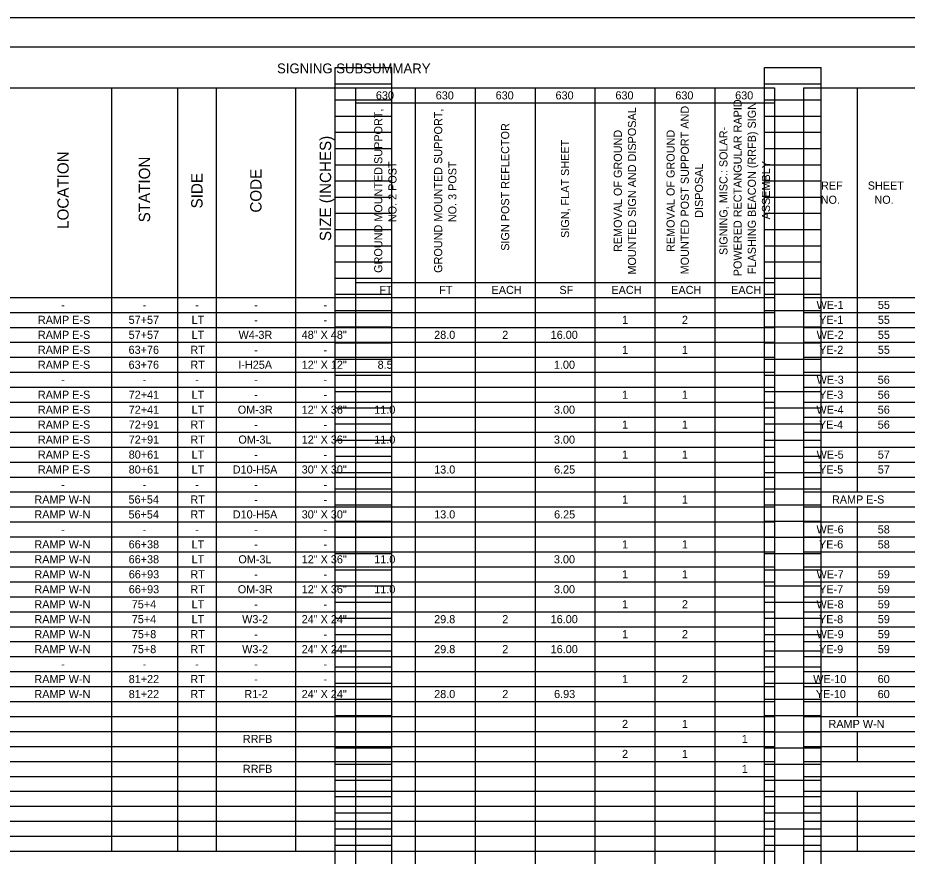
# Model space of a CAD drawing. Extents: x -6.8 to 34, y 0 to 22.
# Drawn here: x 3.36 to 18.73, y 7.51 to 22 of the extents above; entities that cross this region are included whole.
import ezdxf

# ---------------------------------------------------------------- set-up
doc = ezdxf.new("R2010")
doc.units = 0
for name, color, linetype in [('SH_Border', 7, 'Continuous'), ('SH_Cut_Line', 7, 'Continuous'), ('SH_Data', 7, 'Continuous'), ('SH_Text', 7, 'Continuous')]:
    doc.layers.add(name, color=color, linetype=linetype)

msp = doc.modelspace()

# ---------------------------------------------------------------- linework, layer by layer
at = {"layer": 'SH_Border'}
msp.add_lwpolyline([(1.5, 21.5), (33.5, 21.5), (33.5, 0.5), (1.5, 0.5)], close=True, dxfattribs=at)
at = {"layer": 'SH_Cut_Line'}
msp.add_lwpolyline([(0, 0), (34, 0), (34, 22), (0, 22)], close=True, dxfattribs=at)
at = {"layer": 'SH_Data'}
for p, q in [((8.84, 0.98), (8.84, 21.14)), ((8.84, 21.14), (9.82, 21.14)), ((9.82, 0.98), (9.82, 21.14)), ((16.26, 0.98), (16.26, 21.14)), ((16.26, 21.14), (17.24, 21.14)), ((17.24, 0.98), (17.24, 21.14)), ((8.84, 20.86), (9.82, 20.86)), ((16.26, 20.86), (17.24, 20.86)), ((8.84, 20.58), (9.82, 20.58)), ((16.26, 20.58), (17.24, 20.58)), ((8.84, 20.3), (9.82, 20.3)), ((16.26, 20.3), (17.24, 20.3)), ((8.84, 20.02), (9.82, 20.02)), ((16.26, 20.02), (17.24, 20.02)), ((8.84, 19.74), (9.82, 19.74)), ((16.26, 19.74), (17.24, 19.74)), ((8.84, 19.46), (9.82, 19.46)), ((16.26, 19.46), (17.24, 19.46)), ((8.84, 19.18), (9.82, 19.18)), ((16.26, 19.18), (17.24, 19.18)), ((8.84, 18.9), (9.82, 18.9)), ((16.26, 18.9), (17.24, 18.9)), ((8.84, 18.62), (9.82, 18.62)), ((16.26, 18.62), (17.24, 18.62)), ((8.84, 18.34), (9.82, 18.34)), ((16.26, 18.34), (17.24, 18.34)), ((8.84, 18.06), (9.82, 18.06)), ((16.26, 18.06), (17.24, 18.06)), ((8.84, 17.78), (9.82, 17.78)), ((16.26, 17.78), (17.24, 17.78)), ((8.84, 17.5), (9.82, 17.5)), ((16.26, 17.5), (17.24, 17.5)), ((8.84, 17.22), (9.82, 17.22)), ((16.26, 17.22), (17.24, 17.22)), ((8.84, 16.94), (9.82, 16.94)), ((16.26, 16.94), (17.24, 16.94)), ((8.84, 16.66), (9.82, 16.66)), ((16.26, 16.66), (17.24, 16.66)), ((8.84, 16.38), (9.82, 16.38)), ((16.26, 16.38), (17.24, 16.38)), ((8.84, 16.1), (9.82, 16.1)), ((16.26, 16.1), (17.24, 16.1)), ((8.84, 15.82), (9.82, 15.82)), ((16.26, 15.82), (17.24, 15.82)), ((8.84, 15.54), (9.82, 15.54)), ((16.26, 15.54), (17.24, 15.54)), ((8.84, 15.26), (9.82, 15.26)), ((16.26, 15.26), (17.24, 15.26)), ((8.84, 14.98), (9.82, 14.98)), ((16.26, 14.98), (17.24, 14.98)), ((8.84, 14.7), (9.82, 14.7)), ((16.26, 14.7), (17.24, 14.7)), ((8.84, 14.42), (9.82, 14.42)), ((16.26, 14.42), (17.24, 14.42)), ((8.84, 14.14), (9.82, 14.14)), ((16.26, 14.14), (17.24, 14.14)), ((8.84, 13.86), (9.82, 13.86)), ((16.26, 13.86), (17.24, 13.86)), ((8.84, 13.58), (9.82, 13.58)), ((16.26, 13.58), (17.24, 13.58)), ((8.84, 13.3), (9.82, 13.3)), ((16.26, 13.3), (17.24, 13.3)), ((8.84, 13.02), (9.82, 13.02)), ((16.26, 13.02), (17.24, 13.02)), ((8.84, 12.74), (9.82, 12.74)), ((16.26, 12.74), (17.24, 12.74)), ((8.84, 12.46), (9.82, 12.46)), ((16.26, 12.46), (17.24, 12.46)), ((8.84, 12.18), (9.82, 12.18)), ((16.26, 12.18), (17.24, 12.18)), ((8.84, 11.9), (9.82, 11.9)), ((16.26, 11.9), (17.24, 11.9)), ((8.84, 11.62), (9.82, 11.62)), ((16.26, 11.62), (17.24, 11.62)), ((8.84, 11.34), (9.82, 11.34)), ((16.26, 11.34), (17.24, 11.34)), ((8.84, 11.06), (9.82, 11.06)), ((16.26, 11.06), (17.24, 11.06)), ((8.84, 10.78), (9.82, 10.78)), ((16.26, 10.78), (17.24, 10.78)), ((8.84, 10.5), (9.82, 10.5)), ((16.26, 10.5), (17.24, 10.5)), ((8.84, 10.22), (9.82, 10.22)), ((16.26, 10.22), (17.24, 10.22)), ((8.84, 9.94), (9.82, 9.94)), ((16.26, 9.94), (17.24, 9.94)), ((8.84, 9.66), (9.82, 9.66)), ((16.26, 9.66), (17.24, 9.66)), ((8.84, 9.38), (9.82, 9.38)), ((16.26, 9.38), (17.24, 9.38)), ((8.84, 9.1), (9.82, 9.1)), ((16.26, 9.1), (17.24, 9.1)), ((8.84, 8.82), (9.82, 8.82)), ((16.26, 8.82), (17.24, 8.82)), ((8.84, 8.54), (9.82, 8.54)), ((16.26, 8.54), (17.24, 8.54)), ((8.84, 8.26), (9.82, 8.26)), ((16.26, 8.26), (17.24, 8.26)), ((8.84, 7.98), (9.82, 7.98)), ((16.26, 7.98), (17.24, 7.98)), ((8.84, 7.7), (9.82, 7.7)), ((16.26, 7.7), (17.24, 7.7))]:
    msp.add_line(p, q, dxfattribs=at)
at = {"layer": 'SH_Text'}
for p, q in [((1.872, 20.788), (16.435, 20.788)), ((4.977, 20.788), (4.977, 7.595)), ((6.118, 20.788), (6.118, 7.595)), ((6.788, 20.788), (6.788, 7.595)), ((8.157, 20.788), (8.157, 7.595)), ((9.192, 20.788), (9.192, 7.078)), ((10.227, 20.788), (10.227, 7.078)), ((11.262, 20.788), (11.262, 7.078)), ((12.296, 20.788), (12.296, 7.078)), ((13.331, 20.788), (13.331, 7.078)), ((14.366, 20.788), (14.366, 7.078)), ((15.401, 20.788), (15.401, 7.078)), ((16.435, 20.788), (16.435, 7.078)), ((16.932, 20.788), (31.662, 20.788)), ((16.932, 20.788), (16.932, 7.078)), ((17.86, 20.788), (17.86, 13.804)), ((9.192, 20.53), (16.435, 20.53)), ((9.192, 17.425), (16.435, 17.425)), ((1.872, 17.167), (16.435, 17.167)), ((16.932, 17.167), (31.662, 17.167)), ((1.872, 16.908), (16.435, 16.908)), ((16.932, 16.908), (31.662, 16.908)), ((1.872, 16.649), (16.435, 16.649)), ((16.932, 16.649), (31.662, 16.649)), ((1.872, 16.391), (16.435, 16.391)), ((16.932, 16.391), (31.662, 16.391)), ((1.872, 16.132), (16.435, 16.132)), ((16.932, 16.132), (31.662, 16.132)), ((1.872, 15.873), (16.435, 15.873)), ((16.932, 15.873), (31.662, 15.873)), ((1.872, 15.615), (16.435, 15.615)), ((16.932, 15.615), (31.662, 15.615)), ((1.872, 15.356), (16.435, 15.356)), ((16.932, 15.356), (31.662, 15.356)), ((1.872, 15.097), (16.435, 15.097)), ((16.932, 15.097), (31.662, 15.097)), ((1.872, 14.838), (16.435, 14.838)), ((16.932, 14.838), (31.662, 14.838)), ((1.872, 14.58), (16.435, 14.58)), ((16.932, 14.58), (31.662, 14.58)), ((1.872, 14.321), (16.435, 14.321)), ((16.932, 14.321), (31.662, 14.321)), ((1.872, 14.062), (16.435, 14.062)), ((16.932, 14.062), (31.662, 14.062)), ((1.872, 13.804), (16.435, 13.804)), ((16.932, 13.804), (31.662, 13.804)), ((1.872, 13.545), (16.435, 13.545)), ((16.932, 13.545), (31.662, 13.545)), ((17.86, 13.545), (17.86, 9.923)), ((1.872, 13.286), (16.435, 13.286)), ((16.932, 13.286), (31.662, 13.286)), ((1.872, 13.028), (16.435, 13.028)), ((16.932, 13.028), (31.662, 13.028)), ((1.872, 12.769), (16.435, 12.769)), ((16.932, 12.769), (31.662, 12.769)), ((1.872, 12.51), (16.435, 12.51)), ((16.932, 12.51), (31.662, 12.51)), ((1.872, 12.251), (16.435, 12.251)), ((16.932, 12.251), (31.662, 12.251)), ((1.872, 11.993), (16.435, 11.993)), ((16.932, 11.993), (31.662, 11.993)), ((1.872, 11.734), (16.435, 11.734)), ((16.932, 11.734), (31.662, 11.734)), ((1.872, 11.475), (16.435, 11.475)), ((16.932, 11.475), (31.662, 11.475)), ((1.872, 11.217), (16.435, 11.217)), ((16.932, 11.217), (31.662, 11.217)), ((1.872, 10.958), (16.435, 10.958)), ((16.932, 10.958), (31.662, 10.958)), ((1.872, 10.699), (16.435, 10.699)), ((16.932, 10.699), (31.662, 10.699)), ((1.872, 10.441), (16.435, 10.441)), ((16.932, 10.441), (31.662, 10.441)), ((1.872, 10.182), (16.435, 10.182)), ((16.932, 10.182), (31.662, 10.182)), ((1.872, 9.923), (16.435, 9.923)), ((16.932, 9.923), (31.662, 9.923)), ((1.872, 9.665), (16.435, 9.665)), ((16.932, 9.665), (31.662, 9.665)), ((17.86, 9.665), (17.86, 9.147)), ((1.872, 9.406), (16.435, 9.406)), ((16.932, 9.406), (31.662, 9.406)), ((1.872, 9.147), (16.435, 9.147)), ((16.932, 9.147), (31.662, 9.147)), ((1.872, 8.888), (16.435, 8.888)), ((16.932, 8.888), (31.662, 8.888)), ((1.872, 8.63), (16.435, 8.63)), ((16.932, 8.63), (31.662, 8.63)), ((17.86, 8.63), (17.86, 7.595)), ((1.872, 8.371), (16.435, 8.371)), ((16.932, 8.371), (31.662, 8.371)), ((1.872, 8.112), (16.435, 8.112)), ((16.932, 8.112), (31.662, 8.112)), ((1.872, 7.854), (16.435, 7.854)), ((16.932, 7.854), (31.662, 7.854)), ((1.872, 7.595), (9.192, 7.595)), ((9.192, 7.595), (16.435, 7.595)), ((16.932, 7.595), (31.662, 7.595))]:
    msp.add_line(p, q, dxfattribs=at)

# ---------------------------------------------------------------- texts
for s, height, p in [('SIGNING SUBSUMMARY', 0.17, (7.838, 21.04)), ('630', 0.14, (9.546, 20.589)), ('630', 0.14, (10.58, 20.589)), ('630', 0.14, (11.615, 20.589)), ('630', 0.14, (12.65, 20.589)), ('630', 0.14, (13.685, 20.589)), ('630', 0.14, (14.72, 20.589)), ('630', 0.14, (15.754, 20.589)), ('REF', 0.14, (17.237, 19.03)), ('SHEET', 0.14, (18.044, 19.03)), ('NO.', 0.14, (17.232, 18.785)), ('NO.', 0.14, (18.16, 18.785)), ('FT', 0.14, (9.606, 17.226)), ('FT', 0.14, (10.641, 17.226)), ('EACH', 0.14, (11.545, 17.226)), ('SF', 0.14, (12.717, 17.226)), ('EACH', 0.14, (13.615, 17.226)), ('EACH', 0.14, (14.649, 17.226)), ('EACH', 0.14, (15.684, 17.226)), ('WE-1', 0.14, (17.16, 16.967)), ('55', 0.14, (18.219, 16.967)), ('-', 0.14, (4.11, 16.967)), ('-', 0.14, (5.517, 16.967)), ('-', 0.14, (6.423, 16.967)), ('-', 0.14, (7.442, 16.967)), ('-', 0.14, (8.644, 16.967)), ('RAMP E-S', 0.14, (3.706, 16.709)), ('57+57', 0.14, (5.274, 16.709)), ('LT', 0.14, (6.362, 16.709)), ('-', 0.14, (7.442, 16.709)), ('-', 0.14, (8.644, 16.709)), ('1', 0.14, (13.799, 16.709)), ('2', 0.14, (14.834, 16.709)), ('YE-1', 0.14, (17.205, 16.709)), ('55', 0.14, (18.219, 16.709)), ('RAMP E-S', 0.14, (3.706, 16.45)), ('57+57', 0.14, (5.274, 16.45)), ('LT', 0.14, (6.362, 16.45)), ('W4-3R', 0.14, (7.173, 16.45)), ('48" X 48"', 0.14, (8.264, 16.45)), ('28.0', 0.14, (10.553, 16.45)), ('2', 0.14, (11.729, 16.45)), ('16.00', 0.14, (12.566, 16.45)), ('WE-2', 0.14, (17.161, 16.45)), ('55', 0.14, (18.219, 16.45)), ('RAMP E-S', 0.14, (3.706, 16.191)), ('63+76', 0.14, (5.273, 16.191)), ('RT', 0.14, (6.341, 16.191)), ('1', 0.14, (13.799, 16.191)), ('1', 0.14, (14.833, 16.191)), ('YE-2', 0.14, (17.205, 16.191)), ('55', 0.14, (18.219, 16.191)), ('-', 0.14, (7.442, 16.191)), ('-', 0.14, (8.644, 16.191)), ('RAMP E-S', 0.14, (3.706, 15.933)), ('63+76', 0.14, (5.273, 15.933)), ('RT', 0.14, (6.341, 15.933)), ('I-H25A', 0.14, (7.169, 15.933)), ('12" X 12"', 0.14, (8.264, 15.933)), ('8.5', 0.14, (9.576, 15.933)), ('1.00', 0.14, (12.622, 15.933)), ('-', 0.14, (4.11, 15.674)), ('-', 0.14, (5.517, 15.674)), ('-', 0.14, (6.423, 15.674)), ('-', 0.14, (7.442, 15.674)), ('-', 0.14, (8.644, 15.674)), ('WE-3', 0.14, (17.161, 15.674)), ('56', 0.14, (18.217, 15.674)), ('RAMP E-S', 0.14, (3.706, 15.415)), ('72+41', 0.14, (5.275, 15.415)), ('LT', 0.14, (6.362, 15.415)), ('1', 0.14, (13.799, 15.415)), ('1', 0.14, (14.833, 15.415)), ('YE-3', 0.14, (17.206, 15.415)), ('56', 0.14, (18.217, 15.415)), ('-', 0.14, (7.442, 15.415)), ('-', 0.14, (8.644, 15.415)), ('RAMP E-S', 0.14, (3.706, 15.156)), ('72+41', 0.14, (5.275, 15.156)), ('LT', 0.14, (6.362, 15.156)), ('OM-3R', 0.14, (7.16, 15.156)), ('12" X 36"', 0.14, (8.264, 15.156)), ('11.0', 0.14, (9.518, 15.156)), ('3.00', 0.14, (12.622, 15.156)), ('WE-4', 0.14, (17.158, 15.156)), ('56', 0.14, (18.217, 15.156)), ('RAMP E-S', 0.14, (3.706, 14.898)), ('72+91', 0.14, (5.275, 14.898)), ('RT', 0.14, (6.341, 14.898)), ('-', 0.14, (7.442, 14.898)), ('-', 0.14, (8.644, 14.898)), ('1', 0.14, (13.799, 14.898)), ('1', 0.14, (14.833, 14.898)), ('YE-4', 0.14, (17.202, 14.898)), ('56', 0.14, (18.217, 14.898)), ('RAMP E-S', 0.14, (3.706, 14.639)), ('72+91', 0.14, (5.275, 14.639)), ('RT', 0.14, (6.341, 14.639)), ('OM-3L', 0.14, (7.17, 14.639)), ('12" X 36"', 0.14, (8.264, 14.639)), ('11.0', 0.14, (9.518, 14.639)), ('3.00', 0.14, (12.622, 14.639)), ('RAMP E-S', 0.14, (3.706, 14.38)), ('80+61', 0.14, (5.275, 14.38)), ('LT', 0.14, (6.362, 14.38)), ('1', 0.14, (13.799, 14.38)), ('1', 0.14, (14.833, 14.38)), ('WE-5', 0.14, (17.161, 14.38)), ('57', 0.14, (18.218, 14.38)), ('-', 0.14, (7.442, 14.38)), ('-', 0.14, (8.644, 14.38)), ('RAMP E-S', 0.14, (3.706, 14.122)), ('80+61', 0.14, (5.275, 14.122)), ('LT', 0.14, (6.362, 14.122)), ('D10-H5A', 0.14, (7.073, 14.122)), ('30" X 30"', 0.14, (8.264, 14.122)), ('13.0', 0.14, (10.553, 14.122)), ('6.25', 0.14, (12.625, 14.122)), ('YE-5', 0.14, (17.205, 14.122)), ('57', 0.14, (18.218, 14.122)), ('-', 0.14, (4.11, 13.863)), ('-', 0.14, (5.517, 13.863)), ('-', 0.14, (6.423, 13.863)), ('-', 0.14, (7.442, 13.863)), ('-', 0.14, (8.644, 13.863)), ('RAMP W-N', 0.14, (3.646, 13.604)), ('56+54', 0.14, (5.272, 13.604)), ('RT', 0.14, (6.341, 13.604)), ('1', 0.14, (13.799, 13.604)), ('1', 0.14, (14.833, 13.604)), ('RAMP E-S', 0.14, (17.426, 13.604)), ('-', 0.14, (7.442, 13.604)), ('-', 0.14, (8.644, 13.604)), ('RAMP W-N', 0.14, (3.646, 13.346)), ('56+54', 0.14, (5.272, 13.346)), ('RT', 0.14, (6.341, 13.346)), ('D10-H5A', 0.14, (7.073, 13.346)), ('30" X 30"', 0.14, (8.264, 13.346)), ('13.0', 0.14, (10.553, 13.346)), ('6.25', 0.14, (12.625, 13.346)), ('WE-6', 0.14, (17.159, 13.087)), ('58', 0.14, (18.217, 13.087)), ('-', 0.14, (4.11, 13.087)), ('-', 0.14, (5.517, 13.087)), ('-', 0.14, (6.423, 13.087)), ('-', 0.14, (7.442, 13.087)), ('-', 0.14, (8.644, 13.087)), ('RAMP W-N', 0.14, (3.646, 12.828)), ('66+38', 0.14, (5.274, 12.828)), ('LT', 0.14, (6.362, 12.828)), ('1', 0.14, (13.799, 12.828)), ('1', 0.14, (14.833, 12.828)), ('YE-6', 0.14, (17.203, 12.828)), ('58', 0.14, (18.217, 12.828)), ('-', 0.14, (7.442, 12.828)), ('-', 0.14, (8.644, 12.828)), ('RAMP W-N', 0.14, (3.646, 12.57)), ('66+38', 0.14, (5.274, 12.57)), ('LT', 0.14, (6.362, 12.57)), ('OM-3L', 0.14, (7.17, 12.57)), ('12" X 36"', 0.14, (8.264, 12.57)), ('11.0', 0.14, (9.518, 12.57)), ('3.00', 0.14, (12.622, 12.57)), ('RAMP W-N', 0.14, (3.646, 12.311)), ('66+93', 0.14, (5.276, 12.311)), ('RT', 0.14, (6.341, 12.311)), ('1', 0.14, (13.799, 12.311)), ('1', 0.14, (14.833, 12.311)), ('WE-7', 0.14, (17.16, 12.311)), ('59', 0.14, (18.218, 12.311)), ('-', 0.14, (7.442, 12.311)), ('-', 0.14, (8.644, 12.311)), ('RAMP W-N', 0.14, (3.646, 12.052)), ('66+93', 0.14, (5.276, 12.052)), ('RT', 0.14, (6.341, 12.052)), ('OM-3R', 0.14, (7.16, 12.052)), ('12" X 36"', 0.14, (8.264, 12.052)), ('11.0', 0.14, (9.518, 12.052)), ('3.00', 0.14, (12.622, 12.052)), ('YE-7', 0.14, (17.204, 12.052)), ('59', 0.14, (18.218, 12.052)), ('RAMP W-N', 0.14, (3.646, 11.793)), ('75+4', 0.14, (5.328, 11.793)), ('LT', 0.14, (6.362, 11.793)), ('-', 0.14, (7.442, 11.793)), ('-', 0.14, (8.644, 11.793)), ('1', 0.14, (13.799, 11.793)), ('2', 0.14, (14.834, 11.793)), ('WE-8', 0.14, (17.159, 11.793)), ('59', 0.14, (18.218, 11.793)), ('RAMP W-N', 0.14, (3.646, 11.535)), ('75+4', 0.14, (5.328, 11.535)), ('LT', 0.14, (6.362, 11.535)), ('W3-2', 0.14, (7.235, 11.535)), ('24" X 24"', 0.14, (8.264, 11.535)), ('29.8', 0.14, (10.553, 11.535)), ('2', 0.14, (11.729, 11.535)), ('16.00', 0.14, (12.566, 11.535)), ('YE-8', 0.14, (17.203, 11.535)), ('59', 0.14, (18.218, 11.535)), ('RAMP W-N', 0.14, (3.646, 11.276)), ('75+8', 0.14, (5.329, 11.276)), ('RT', 0.14, (6.341, 11.276)), ('1', 0.14, (13.799, 11.276)), ('2', 0.14, (14.834, 11.276)), ('WE-9', 0.14, (17.16, 11.276)), ('59', 0.14, (18.218, 11.276)), ('-', 0.14, (7.442, 11.276)), ('-', 0.14, (8.644, 11.276)), ('RAMP W-N', 0.14, (3.646, 11.017)), ('75+8', 0.14, (5.329, 11.017)), ('RT', 0.14, (6.341, 11.017)), ('W3-2', 0.14, (7.235, 11.017)), ('24" X 24"', 0.14, (8.264, 11.017)), ('29.8', 0.14, (10.553, 11.017)), ('2', 0.14, (11.729, 11.017)), ('16.00', 0.14, (12.566, 11.017)), ('YE-9', 0.14, (17.204, 11.017)), ('59', 0.14, (18.218, 11.017)), ('-', 0.14, (4.11, 10.759)), ('-', 0.14, (5.517, 10.759)), ('-', 0.14, (6.423, 10.759)), ('-', 0.14, (7.442, 10.759)), ('-', 0.14, (8.644, 10.759)), ('RAMP W-N', 0.14, (3.646, 10.5)), ('81+22', 0.14, (5.275, 10.5)), ('RT', 0.14, (6.341, 10.5)), ('1', 0.14, (13.799, 10.5)), ('2', 0.14, (14.834, 10.5)), ('WE-10', 0.14, (17.102, 10.5)), ('60', 0.14, (18.216, 10.5)), ('-', 0.14, (7.442, 10.5)), ('-', 0.14, (8.644, 10.5)), ('RAMP W-N', 0.14, (3.646, 10.241)), ('81+22', 0.14, (5.275, 10.241)), ('RT', 0.14, (6.341, 10.241)), ('R1-2', 0.14, (7.273, 10.241)), ('24" X 24"', 0.14, (8.264, 10.241)), ('28.0', 0.14, (10.553, 10.241)), ('2', 0.14, (11.729, 10.241)), ('6.93', 0.14, (12.625, 10.241)), ('YE-10', 0.14, (17.147, 10.241)), ('60', 0.14, (18.216, 10.241)), ('2', 0.14, (13.799, 9.724)), ('1', 0.14, (14.833, 9.724)), ('RAMP W-N', 0.14, (17.367, 9.724)), ('RRFB', 0.14, (7.247, 9.465)), ('1', 0.14, (15.868, 9.465)), ('2', 0.14, (13.799, 9.206)), ('1', 0.14, (14.833, 9.206)), ('RRFB', 0.14, (7.247, 8.948)), ('1', 0.14, (15.868, 8.948))]:
    msp.add_text(s, height=height, dxfattribs=at).set_placement(p)
for s, height, p in [('MOUNTED SIGN AND DISPOSAL', 0.14, (14.041, 17.561)), ('MOUNTED POST SUPPORT AND ', 0.14, (14.953, 17.565)), ('POWERED RECTANGULAR RAPID ', 0.14, (15.866, 17.532)), ('FLASHING BEACON (RRFB) SIGN ', 0.14, (16.111, 17.569)), ('GROUND MOUNTED SUPPORT, ', 0.14, (9.657, 17.591)), ('GROUND MOUNTED SUPPORT, ', 0.14, (10.692, 17.591)), ('SIGN POST REFLECTOR', 0.14, (11.849, 17.973)), ('REMOVAL OF GROUND ', 0.14, (13.796, 17.951)), ('REMOVAL OF GROUND ', 0.14, (14.708, 17.951)), ('SIGNING, MISC.: SOLAR-', 0.14, (15.621, 17.9)), ('SIZE (INCHES)', 0.196, (8.773, 18.14)), ('SIGN, FLAT SHEET', 0.14, (12.884, 18.195)), ('LOCATION', 0.196, (4.238, 18.351)), ('STATION', 0.196, (5.645, 18.464)), ('ASSEMBLY', 0.14, (16.356, 18.515)), ('CODE', 0.196, (7.57, 18.632)), ('NO. 2 POST', 0.14, (9.902, 18.467)), ('NO. 3 POST', 0.14, (10.937, 18.467)), ('DISPOSAL', 0.14, (15.198, 18.542)), ('SIDE', 0.196, (6.551, 18.705))]:
    msp.add_text(s, height=height, rotation=90, dxfattribs=at).set_placement(p)

doc.saveas('drawing.dxf')
